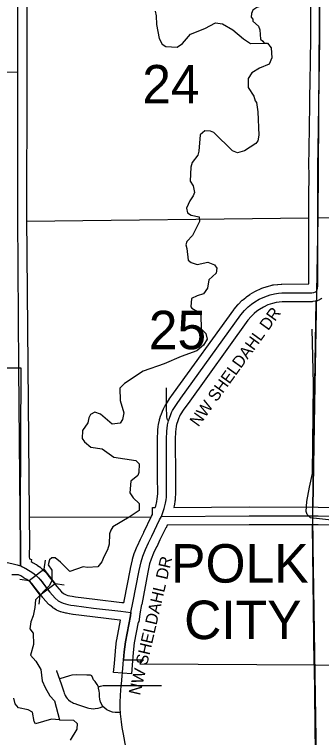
# Model space of a CAD drawing. Extents: x -1403959 to 81668, y -1400582 to 11018.
# Drawn here: x 6704.7 to 6804.9, y 9533.5 to 9769.7 of the extents above; entities that cross this region are included whole.
import ezdxf

# ---------------------------------------------------------------- set-up
doc = ezdxf.new("R2010")
doc.units = 0
for name, color, linetype in [('tdCiCityCartoExten', 7, 'Continuous'), ('tdCiCoBndryTxt', 7, 'Continuous'), ('tdCiMapFrame', 7, 'Continuous'), ('tdCiRRCL', 7, 'Continuous'), ('tdCiSecText', 7, 'Continuous'), ('tdCiSectLine', 7, 'Continuous'), ('tdCiSectNmbr', 7, 'Continuous'), ('tdCiSectTwpRng', 7, 'Continuous'), ('tdCoCityStreetMajor', 7, 'Continuous'), ('tdCoClipBndry', 7, 'Continuous'), ('tdCoSectLinePart', 7, 'Continuous'), ('tdCoSectNmbr', 7, 'Continuous'), ('tdCoShieldCoRteHrd', 7, 'Continuous'), ('tdCoSurfBitum', 7, 'Continuous'), ('tdCoTwpNameTxt', 7, 'Continuous')]:
    doc.layers.add(name, color=color, linetype=linetype)

msp = doc.modelspace()

# ---------------------------------------------------------------- linework, layer by layer
at = {"layer": 'tdCiCityCartoExten'}
msp.add_lwpolyline([(6754.95, 9636.92), (6754.6, 9637.29), (6754.52, 9637.72), (6754.46, 9638.16), (6754.42, 9638.6), (6754.36, 9641.16), (6754.27, 9647.8)], dxfattribs=at)
at = {"layer": 'tdCiCoBndryTxt'}
for points in [[(6706.2, 9654.39), (6705.79, 9703.38), (6705.84, 9750.93), (6705.82, 9781.7), (6705.86, 9796.01), (6705.88, 9799.28)], [(6803.35, 9679.53), (6803.48, 9679.75), (6803.62, 9680.23), (6803.67, 9681.02), (6803.69, 9689.78), (6803.69, 9703.36), (6803.69, 9707.13), (6803.71, 9709.84), (6803.72, 9717.82), (6803.7, 9720.21), (6803.75, 9725.87), (6803.86, 9732.82), (6803.97, 9740.29), (6803.99, 9742.53), (6804.08, 9747.62), (6804.19, 9754.41), (6804.33, 9761.91), (6804.36, 9769.25), (6804.34, 9776.67)], [(6742.74, 9574.37), (6743.38, 9577.54), (6745.4, 9588.12), (6746.01, 9590.95), (6746.57, 9592.76), (6747.45, 9594.9), (6748.5, 9597.06), (6749.53, 9599.32), (6752.08, 9604.58), (6752.64, 9605.76), (6753.16, 9607.01), (6753.61, 9608.28), (6754.05, 9610.06), (6754.21, 9611.16), (6754.28, 9612.07), (6754.35, 9613.16), (6754.34, 9618.68), (6754.3, 9630.89), (6754.38, 9633.74), (6754.49, 9634.5), (6754.64, 9635.66), (6754.83, 9636.55), (6754.95, 9636.92), (6755.26, 9637.89), (6755.71, 9639.09), (6755.98, 9639.66), (6756.3, 9640.31), (6757.61, 9642.35), (6759, 9644.33), (6778.6, 9671.57), (6779.8, 9673.04), (6780.97, 9674.16), (6782.05, 9675.1), (6783.11, 9675.83), (6784.6, 9676.72), (6786.37, 9677.53), (6788.1, 9678.09), (6789.53, 9678.51), (6790.81, 9678.65), (6791.93, 9678.73), (6801.69, 9678.77), (6802.42, 9678.88), (6802.92, 9679.08), (6803.23, 9679.33), (6803.35, 9679.53)], [(6706.2, 9654.19), (6706.2, 9654.39)], [(6706.74, 9589.61), (6706.66, 9592.5), (6706.7, 9597.05), (6706.7, 9600.21), (6706.62, 9602.31), (6706.6, 9606.56), (6706.2, 9654.19)], [(6752.64, 9605.76), (6781.28, 9605.92), (6803.79, 9605.89)], [(6803.79, 9605.89), (6825.95, 9605.74), (6848.57, 9605.59), (6866.25, 9605.44), (6899.63, 9605.26)], [(6682.43, 9604.35), (6683.52, 9603.49), (6684.76, 9602), (6685.9, 9600.1), (6686.91, 9598.4), (6688.01, 9596.68), (6688.93, 9595.62), (6689.96, 9594.75), (6691.12, 9593.9), (6691.89, 9593.42), (6692.72, 9593.01), (6693.61, 9592.62), (6694.4, 9592.39), (6695.53, 9592.1), (6698.79, 9591.43), (6703.91, 9590.34), (6705.61, 9589.9), (6706.71, 9589.6)], [(6706.71, 9589.6), (6706.74, 9589.59)], [(6706.74, 9589.59), (6706.74, 9589.61)], [(6706.74, 9589.59), (6706.82, 9589.55)], [(6706.82, 9589.55), (6707.33, 9589.28), (6708.16, 9588.87), (6709.32, 9588.14), (6710.41, 9587.52), (6711.18, 9586.94), (6711.82, 9586.4), (6712.57, 9585.72), (6713.34, 9584.8), (6715.43, 9582.11), (6716.11, 9581.22)], [(6716.11, 9581.22), (6716.15, 9581.17)], [(6716.15, 9581.17), (6716.28, 9580.99), (6718.04, 9579), (6719.03, 9578.21), (6719.84, 9577.7), (6720.65, 9577.36), (6721.4, 9577.14), (6722.16, 9576.95), (6723.08, 9576.8), (6724.22, 9576.62), (6730.54, 9575.79), (6739.4, 9574.77), (6742.74, 9574.37)], [(6740.33, 9558.86), (6740.54, 9561.51), (6740.92, 9564.82), (6742.54, 9573.3), (6742.73, 9574.32)], [(6742.73, 9574.32), (6742.74, 9574.37)], [(6740.21, 9557.41), (6740.22, 9557.57)], [(6740.22, 9557.57), (6740.33, 9558.86)]]:
    msp.add_lwpolyline(points, dxfattribs=at)
at = {"layer": 'tdCiMapFrame'}
for points in [[(6635.76, 9750.44), (6675.55, 9750.78), (6705.84, 9750.93)], [(6803.69, 9703.36), (6828.07, 9703.03), (6865.94, 9702.63), (6900.01, 9702.18), (6900.12, 9702.18), (6975.47, 9702.05), (6997.78, 9701.99), (6997.83, 9701.99), (7085, 9700.96), (7095.17, 9700.78)]]:
    msp.add_lwpolyline(points, dxfattribs=at)
at = {"layer": 'tdCiRRCL'}
msp.add_lwpolyline([(6682.14, 9654.23), (6706.76, 9654.24), (6706.6, 9606.56), (6706.62, 9602.31), (6706.7, 9600.21), (6706.7, 9597.05), (6706.66, 9592.5), (6706.74, 9589.61), (6706.74, 9589.59), (6708.39, 9588.7), (6710.75, 9587.26), (6711.69, 9586.57), (6712.23, 9586.01), (6713.06, 9585.14), (6713.72, 9584.34), (6713.94, 9584.05), (6716.1, 9581.22), (6716.28, 9580.99), (6718.04, 9579), (6719.03, 9578.21), (6719.84, 9577.7), (6720.65, 9577.36), (6721.4, 9577.14), (6722.16, 9576.95), (6723.08, 9576.8), (6724.22, 9576.62), (6730.54, 9575.79), (6739.4, 9574.77), (6742.74, 9574.37), (6742.54, 9573.3), (6740.92, 9564.82), (6740.54, 9561.51), (6740.34, 9558.88), (6741.26, 9558.88), (6746.83, 9558.84), (6745.6, 9557.57), (6802.77, 9557.25), (6826.88, 9557.07)], dxfattribs=at)
at = {"layer": 'tdCiSecText'}
for points in [[(6714.69, 9591.46), (6714.3, 9588.53), (6717.97, 9583.72)], [(6706.49, 9585.26), (6709.49, 9584.86), (6714.3, 9588.53)], [(6712.76, 9577.05), (6713.16, 9580.05), (6709.49, 9584.86)], [(6720.97, 9583.32), (6717.97, 9583.72), (6713.16, 9580.05)]]:
    msp.add_lwpolyline(points, dxfattribs=at)
at = {"layer": 'tdCiSectLine'}
for points in [[(6708.72, 9781.7), (6708.74, 9753.83), (6708.74, 9753.83), (6708.74, 9750.93), (6708.75, 9748.04), (6708.74, 9748.04), (6708.74, 9748.03), (6708.74, 9748.03), (6708.7, 9703.39), (6709.5, 9606.59), (6709.5, 9606.58), (6709.53, 9602.37), (6709.6, 9600.32), (6709.6, 9600.21), (6709.6, 9597.05), (6709.6, 9597.02), (6709.57, 9592.53), (6709.58, 9591.83), (6710.31, 9591.63), (6710.15, 9591.05), (6710.82, 9590.63), (6711.85, 9590.04), (6711.86, 9590.04), (6712.02, 9589.93), (6712.15, 9589.84), (6712.92, 9589.26), (6712.95, 9589.24), (6713.06, 9589.15), (6713.69, 9588.61), (6713.73, 9588.58), (6713.76, 9588.56), (6714.51, 9587.88), (6714.62, 9587.78), (6714.75, 9587.64), (6714.8, 9587.58), (6715.57, 9586.65), (6715.64, 9586.58), (6717.72, 9583.89), (6717.73, 9583.88), (6717.74, 9583.86), (6718.53, 9582.83), (6720.05, 9581.11), (6720.71, 9580.58), (6721.18, 9580.29), (6721.62, 9580.1), (6722.16, 9579.95), (6722.76, 9579.79), (6723.54, 9579.66), (6724.63, 9579.5), (6730.9, 9578.67), (6739.73, 9577.65), (6739.74, 9577.65), (6740.38, 9577.57)], [(6740.38, 9577.57), (6740.41, 9577.75), (6740.46, 9577.74), (6740.53, 9578.1), (6742.55, 9588.67), (6742.56, 9588.69), (6742.57, 9588.73), (6743.18, 9591.56), (6743.21, 9591.7), (6743.24, 9591.81), (6743.8, 9593.62), (6743.82, 9593.69), (6743.89, 9593.86), (6744.77, 9596), (6744.77, 9596.01), (6744.84, 9596.16), (6745.87, 9598.29), (6746.89, 9600.52), (6746.92, 9600.58), (6749.47, 9605.84), (6749.74, 9606.41), (6749.73, 9608.65), (6750.66, 9608.65), (6750.83, 9609.11), (6751.2, 9610.61), (6751.32, 9611.48), (6751.38, 9612.28), (6751.45, 9613.26), (6751.44, 9618.67), (6751.4, 9630.88), (6751.4, 9630.89), (6751.4, 9630.97), (6751.48, 9633.82), (6751.49, 9633.93), (6751.51, 9634.11), (6751.51, 9634.13), (6751.61, 9634.89), (6751.76, 9636.04), (6751.79, 9636.22), (6751.8, 9636.25), (6751.99, 9637.15), (6752.03, 9637.3), (6752.07, 9637.45), (6752.5, 9638.79), (6752.52, 9638.82), (6752.54, 9638.9), (6752.99, 9640.1), (6753.03, 9640.2), (6753.09, 9640.34), (6753.36, 9640.91), (6753.37, 9640.92), (6753.69, 9641.58), (6753.7, 9641.59), (6753.78, 9641.76), (6753.86, 9641.88), (6755.16, 9643.92), (6755.19, 9643.96), (6755.24, 9644.02), (6756.63, 9646), (6756.64, 9646.02), (6776.25, 9673.27), (6776.3, 9673.34), (6776.35, 9673.41), (6777.55, 9674.87), (6777.62, 9674.95), (6777.75, 9675.09), (6777.79, 9675.13), (6778.95, 9676.25), (6779.05, 9676.34), (6779.07, 9676.36), (6780.15, 9677.29), (6780.28, 9677.4), (6780.4, 9677.49), (6781.46, 9678.22), (6781.49, 9678.24), (6781.62, 9678.32), (6783.12, 9679.21), (6783.15, 9679.23), (6783.32, 9679.32), (6783.39, 9679.36), (6785.16, 9680.17), (6785.26, 9680.21), (6785.44, 9680.28), (6785.47, 9680.29), (6787.2, 9680.85), (6787.29, 9680.88), (6788.72, 9681.3), (6788.78, 9681.31), (6788.96, 9681.36), (6789.15, 9681.39), (6789.21, 9681.39), (6790.49, 9681.53), (6790.59, 9681.54), (6791.71, 9681.63), (6791.74, 9681.63), (6791.92, 9681.64), (6800.77, 9681.67), (6800.78, 9689.78), (6800.79, 9700.46), (6800.79, 9700.5), (6800.75, 9700.5), (6800.79, 9703.38), (6800.79, 9706.26), (6800.79, 9707.13), (6800.79, 9707.15), (6800.81, 9709.85), (6800.82, 9717.81), (6800.8, 9720.19), (6800.8, 9720.21), (6800.8, 9720.24), (6800.85, 9725.9), (6800.85, 9725.92), (6800.96, 9732.87), (6801.07, 9740.32), (6801.09, 9742.55), (6801.09, 9742.58), (6801.18, 9747.67), (6801.29, 9754.45), (6801.29, 9754.46), (6801.43, 9761.94), (6801.46, 9769.25), (6801.44, 9776.67)], [(6805.04, 9677.07), (6804.73, 9676.82), (6804.68, 9676.78), (6804.53, 9676.67), (6804.37, 9676.57), (6804.2, 9676.48), (6804.03, 9676.4), (6804.01, 9676.39), (6803.52, 9676.19), (6803.35, 9676.13), (6803.17, 9676.08), (6802.99, 9676.03), (6802.83, 9676.01), (6802.11, 9675.9), (6802.07, 9675.9), (6801.88, 9675.88), (6801.71, 9675.87), (6792.04, 9675.83), (6791.07, 9675.76), (6790.1, 9675.65), (6788.95, 9675.32), (6787.43, 9674.82), (6785.96, 9674.15), (6784.67, 9673.38), (6783.82, 9672.8), (6782.92, 9672.02), (6781.94, 9671.07), (6780.91, 9669.8), (6761.36, 9642.64), (6760.02, 9640.73), (6758.83, 9638.89), (6758.59, 9638.4), (6758.38, 9637.96), (6758, 9636.94), (6757.64, 9635.8), (6757.5, 9635.17), (6757.36, 9634.12), (6757.36, 9634.11), (6757.28, 9633.5), (6757.2, 9630.85), (6757.24, 9618.69), (6757.24, 9618.68), (6757.25, 9613.17), (6757.25, 9613.16), (6757.24, 9612.98), (6757.17, 9611.88), (6757.17, 9611.88), (6757.17, 9611.85), (6757.1, 9610.94), (6757.08, 9610.79), (6757.08, 9610.77), (6756.93, 9609.66), (6756.9, 9609.49), (6756.87, 9609.35), (6756.7, 9608.68), (6781.27, 9608.82), (6781.28, 9608.82), (6781.29, 9608.82), (6803.79, 9608.79), (6803.81, 9608.79), (6825.97, 9608.64)], [(6825.93, 9602.84), (6803.78, 9602.99), (6781.29, 9603.02), (6754.59, 9602.87), (6754.21, 9601.97), (6754.07, 9602.03), (6752.16, 9598.08), (6751.14, 9595.85), (6751.11, 9595.79), (6750.1, 9593.71), (6749.31, 9591.77), (6748.82, 9590.21), (6748.25, 9587.54), (6746.23, 9576.99), (6746.22, 9576.97), (6746.22, 9576.96), (6745.61, 9573.9), (6745.27, 9571.14), (6745.09, 9571.16), (6743.79, 9564.39), (6743.43, 9561.23), (6743.1, 9557.18), (6742.87, 9554.29), (6737.08, 9554.76), (6737.32, 9557.65), (6737.65, 9561.74), (6737.66, 9561.84), (6738.04, 9565.16), (6738.05, 9565.2), (6738.07, 9565.37), (6739.31, 9571.85), (6739.06, 9571.88), (6730.21, 9572.91), (6730.17, 9572.91), (6723.85, 9573.74), (6723.79, 9573.75), (6722.65, 9573.93), (6722.61, 9573.93), (6721.68, 9574.09), (6721.59, 9574.1), (6721.44, 9574.14), (6720.68, 9574.33), (6720.65, 9574.34), (6720.62, 9574.35), (6719.86, 9574.56), (6719.72, 9574.61), (6719.54, 9574.68), (6719.51, 9574.69), (6718.69, 9575.04), (6718.55, 9575.1), (6718.39, 9575.19), (6718.31, 9575.24), (6717.5, 9575.74), (6717.41, 9575.79), (6717.26, 9575.9), (6717.21, 9575.95), (6716.22, 9576.74), (6716.13, 9576.82), (6715.99, 9576.95), (6715.87, 9577.08), (6714.11, 9579.07), (6714.1, 9579.08), (6713.98, 9579.22), (6713.97, 9579.24), (6713.13, 9580.34), (6711.08, 9582.98), (6710.48, 9583.71), (6709.91, 9584.21), (6709.37, 9584.67), (6708.81, 9585.09), (6707.88, 9585.62), (6707.87, 9585.63), (6707.77, 9585.69), (6706.75, 9586.34), (6706.07, 9586.67), (6703.92, 9586.61)]]:
    msp.add_lwpolyline(points, dxfattribs=at)
at = {"layer": 'tdCiSectNmbr'}
msp.add_lwpolyline([(6741.71, 9527.01), (6741.07, 9530.38), (6740.31, 9534.61), (6739.91, 9536.74), (6739.6, 9538.59), (6739.34, 9541.24), (6739.31, 9541.69), (6739.24, 9542.82), (6739.18, 9544.97), (6739.28, 9547.33), (6739.54, 9550.42), (6739.55, 9550.49), (6739.6, 9551.05), (6740.21, 9557.37), (6740.21, 9557.41)], dxfattribs=at)
at = {"layer": 'tdCiSectTwpRng'}
for points in [[(6718.44, 9555.43), (6718.47, 9555.34)], [(6718.47, 9555.34), (6719.42, 9552.6), (6720.07, 9550.68), (6720.52, 9549.4), (6720.83, 9548.46), (6720.99, 9547.97), (6721.14, 9547.55), (6721.32, 9547.23), (6721.61, 9546.69), (6721.92, 9546.26), (6722.37, 9545.8), (6722.99, 9545.33), (6723.64, 9544.98), (6724.03, 9544.76), (6724.4, 9544.62), (6725.31, 9544.31), (6728.2, 9543.31), (6728.58, 9543.16), (6729, 9543.06), (6729.76, 9542.96), (6730.44, 9542.92), (6731.07, 9542.94), (6731.98, 9543.07), (6732.82, 9543.27), (6733.6, 9543.68)], [(6732.09, 9550.04), (6731.68, 9550.81), (6731, 9551.8), (6730.54, 9552.38), (6730.26, 9552.92), (6729.92, 9553.66), (6729.54, 9553.87), (6728.38, 9553.93), (6724.81, 9553.96), (6723.47, 9553.89), (6722.66, 9553.7), (6719.52, 9552.63)], [(6719.52, 9552.63), (6719.42, 9552.6)], [(6732.09, 9550.04), (6732.79, 9550.24), (6733.64, 9550.46), (6734.46, 9550.54), (6737.85, 9550.49), (6739.55, 9550.49)], [(6739.55, 9550.49), (6744.15, 9550.51), (6749.62, 9550.52)], [(6749.62, 9550.52), (6752.71, 9550.53)], [(6732.11, 9549.95), (6732.09, 9550.04)], [(6739.31, 9541.69), (6737.58, 9541.65), (6736.71, 9541.79), (6735.82, 9542.07), (6734.85, 9542.53), (6733.6, 9543.68), (6732.83, 9545.11), (6732.55, 9546.05), (6732.42, 9546.96), (6732.48, 9547.96), (6732.35, 9548.63), (6732.19, 9549.62), (6732.11, 9549.95)]]:
    msp.add_lwpolyline(points, dxfattribs=at)
at = {"layer": 'tdCoCityStreetMajor'}
for points in [[(6708.67, 9702.21), (6800.75, 9703.26)], [(6802.01, 9608.8), (6803.18, 9676.1)], [(6709.43, 9605.45), (6749.34, 9605.64)], [(6802.5, 9557.25), (6801.99, 9602.99)]]:
    msp.add_lwpolyline(points, dxfattribs=at)
at = {"layer": 'tdCoClipBndry'}
msp.add_lwpolyline([(6804.33, 9800.46), (6803.65, 9703.3), (6801.96, 9605.89), (6803.05, 9508.67), (6803.21, 9401.86), (6803.05, 9368.41), (6803.02, 9363.73), (6802.74, 9304.91), (6803.31, 9207.91), (6802.74, 9153.76), (6802.3, 9111.74)], dxfattribs=at)
at = {"layer": 'tdCoSurfBitum'}
for points in [[(6798.56, 9775.62), (6796.42, 9775.63), (6792.3, 9776.71), (6791.08, 9776.71), (6789.85, 9775.95), (6787.25, 9773.21), (6783.74, 9771.99), (6782.51, 9771.08), (6782.05, 9770.01), (6781.9, 9768.79), (6782.51, 9768.18), (6782.51, 9767.57), (6784.34, 9765.89), (6784.79, 9764.66), (6784.94, 9761.61), (6785.7, 9761), (6786.16, 9760.39)], [(6750.6, 9770.85), (6750.9, 9769.32), (6751.05, 9766.42), (6751.96, 9761.84), (6752.87, 9760), (6754.09, 9759.24), (6757.75, 9759.08), (6759.59, 9760.29), (6762.19, 9763.34), (6766.78, 9765.16), (6770.29, 9766.99), (6772.58, 9766.68), (6775.94, 9764.68), (6779.44, 9761.78), (6781.73, 9760.24), (6786.16, 9760.39), (6787.23, 9760.38), (6788.44, 9758.86), (6788.74, 9755.5), (6787.82, 9753.51), (6784.61, 9752.15), (6782.17, 9750.63), (6780.94, 9748.8), (6780.94, 9745.9), (6782.76, 9742.99), (6783.22, 9741.46), (6783.67, 9741.01), (6784.13, 9737.95), (6784.42, 9730.32), (6784.11, 9728.49), (6783.49, 9727.57), (6779.82, 9725.14), (6777.53, 9724.53), (6775.85, 9725.15), (6769.76, 9731.11), (6768.69, 9731.57), (6766.86, 9731.73), (6765.33, 9730.36), (6764.86, 9725.02), (6764.55, 9723.8), (6762.72, 9721.36), (6762.25, 9719.83), (6762.09, 9715.26), (6763.01, 9713.73), (6763.46, 9711.59), (6763, 9710.52), (6761.93, 9708.84), (6760.85, 9706.4), (6761.15, 9704.88), (6762.37, 9704.11), (6764.97, 9703.65), (6765.12, 9702.12), (6762.82, 9697.55), (6760.98, 9695.57), (6760.68, 9694.5), (6760.98, 9693.28), (6761.43, 9689.46), (6762.34, 9688.69), (6764.33, 9688.08), (6767.84, 9688.83), (6769.98, 9687.91), (6770.74, 9686.84), (6770.58, 9685.16), (6768.13, 9683.03), (6767.67, 9680.28), (6766.44, 9678.46), (6764.31, 9677.85), (6762.47, 9676.94), (6762.31, 9674.19), (6762.62, 9673.73), (6764.45, 9672.66), (6765.51, 9671.44), (6765.66, 9667.01), (6767.18, 9665.48), (6767.64, 9663.65), (6766.41, 9661.66), (6764.27, 9659.84), (6759.07, 9658.02), (6753.57, 9655.59), (6746.7, 9653.16), (6740.58, 9649.2), (6739.05, 9647.68), (6739.19, 9643.56), (6740.41, 9639.59), (6739.94, 9637.45), (6739.18, 9636.23), (6736.58, 9635.93), (6732.77, 9639.15), (6730.94, 9639.76), (6729.56, 9639), (6728.95, 9637.93), (6728.64, 9636.26), (6726.96, 9633.82), (6726.8, 9631.22), (6727.56, 9630.15), (6729.69, 9628.32), (6733.36, 9627.85), (6737.17, 9625.09), (6744.34, 9624.01), (6745.41, 9622.94), (6745.25, 9620.04), (6744.95, 9619.12), (6742.65, 9617.29), (6742.34, 9613.48), (6743.4, 9611.8), (6745.38, 9609.96), (6745.38, 9607.67), (6742.17, 9605.54), (6736.82, 9602.35), (6736.2, 9601.28), (6735.74, 9600.06), (6735.58, 9596.7), (6735.12, 9594.87), (6733.9, 9592.58), (6733.28, 9590.91), (6731.9, 9589.23), (6728.55, 9589.09), (6727.17, 9589.24), (6722.74, 9587.72), (6719.69, 9590.78), (6718.02, 9592.16), (6716.95, 9592.16), (6716.18, 9591.56), (6715.72, 9589.88), (6716.94, 9588.2), (6716.93, 9584.84), (6716.16, 9583.16), (6711.57, 9578.44), (6711.42, 9576), (6710.8, 9573.25), (6710.03, 9571.27), (6709.72, 9568.98), (6710.79, 9567.6), (6710.93, 9563.94), (6710.01, 9560.43), (6711.69, 9558.44), (6713.36, 9555.69), (6713.81, 9552.02), (6714.72, 9549.88), (6716.24, 9547.13), (6717.77, 9545.45), (6719.43, 9539.34), (6724.01, 9539.18), (6725.23, 9538.1), (6725.08, 9536.27), (6722.93, 9532.61)], [(6810.12, 9604.32), (6801.26, 9605.25), (6800.19, 9606.33), (6799.89, 9607.39), (6800.05, 9610.6), (6800.98, 9615.33), (6801.9, 9619.76), (6802.27, 9649.06), (6801.85, 9666.93)], [(6719.43, 9539.34), (6716.84, 9539.5), (6711.64, 9537.98), (6711.19, 9538.75), (6710.58, 9541.8), (6709.21, 9542.57), (6706, 9543.19), (6704.94, 9544.56), (6704.48, 9546.4)]]:
    msp.add_lwpolyline(points, dxfattribs=at)
at = {"layer": 'tdCoTwpNameTxt'}
for points in [[(6803.18, 9675.96), (6802.01, 9608.8)], [(6801.99, 9602.99), (6803.39, 9512.15), (6803.34, 9401.88), (6803.03, 9365.26), (6802.74, 9304.91), (6803.31, 9207.91), (6802.74, 9153.76)]]:
    msp.add_lwpolyline(points, dxfattribs=at)

# ---------------------------------------------------------------- texts
at = {"layer": 'tdCoSectLinePart'}
for s, p in [('24', (6746.42, 9740.64)), ('25', (6748.54, 9660.35))]:
    msp.add_text(s, height=12.575, rotation=359.9921, dxfattribs=at).set_placement(p)
at = {"layer": 'tdCoSectNmbr'}
for rotation, p in [(54.0866, (6764.72, 9634.79)), (76.8235, (6745.68, 9547.1))]:
    msp.add_text('NW SHELDAHL DR', height=3.8691, rotation=rotation, dxfattribs=at).set_placement(p)
at = {"layer": 'tdCoShieldCoRteHrd'}
for s, p in [('POLK', (6755.82, 9584.11)), ('CITY', (6760.07, 9565.66))]:
    msp.add_text(s, height=12.575, rotation=359.9939, dxfattribs=at).set_placement(p)

doc.saveas('drawing.dxf')
